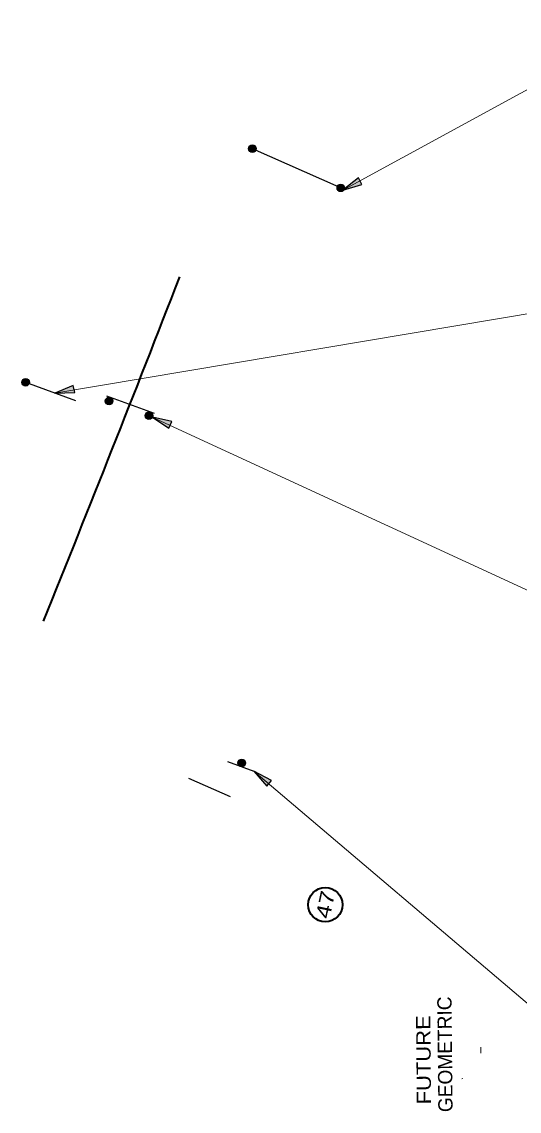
# Model space of a CAD drawing. Extents: x 2363411 to 2369702, y 6977197 to 6988655.
# Drawn here: x 2365294 to 2365781, y 6980619 to 6981687 of the extents above; entities that cross this region are included whole.
import ezdxf
from ezdxf.enums import TextEntityAlignment as Align

# ---------------------------------------------------------------- set-up
doc = ezdxf.new("R2010")
doc.units = 0
doc.header["$LTSCALE"] = 5.6
for name, color, linetype, lineweight in [('1', 7, 'Continuous', 25), ('15', 7, 'Continuous', 13), ('17', 7, 'Continuous', 35), ('23', 7, 'Continuous', 25), ('3', 7, 'Continuous', 13)]:
    doc.layers.add(name, color=color, linetype=linetype, lineweight=lineweight)

msp = doc.modelspace()

# ---------------------------------------------------------------- hatches: boundary and pattern name
at = {"layer": '1'}
for points in [[(2365516.54, 6981560.394, 1), (2365522.419, 6981564.992, 1)], [(2365607.98, 6981522.117), (2365626.692, 6981527.718), (2365623.395, 6981534.116)], [(2365603.151, 6981522.012, 1), (2365609.03, 6981526.609, 1)], [(2365300.1, 6981336.265, 1), (2365294.635, 6981331.182, 1)], [(2365325.995, 6981323.206), (2365345.523, 6981323.654), (2365344.049, 6981330.689)], [(2365381.831, 6981317.867, 1), (2365376.366, 6981312.784, 1)], [(2365420.93, 6981303.592, 1), (2365415.465, 6981298.509, 1)], [(2365421.538, 6981299.498), (2365437.793, 6981288.666), (2365440.62, 6981295.275)], [(2365511.779, 6980963.106, 1), (2365506.314, 6980958.023, 1)], [(2365520.975, 6980952.631), (2365533.575, 6980937.705), (2365538.129, 6980943.266)]]:
    msp.add_hatch(color=256, dxfattribs=at).paths.add_polyline_path(points)

# ---------------------------------------------------------------- linework, layer by layer
for p, q in [((2365604.484, 6981525.128), (2365519.48, 6981562.693)), ((2365297.357, 6981333.718), (2365346.184, 6981315.794)), ((2365376.543, 6981320.437), (2365423.194, 6981303.312)), ((2365495.118, 6980962.133), (2365520.812, 6980952.701))]:
    msp.add_line(p, q, dxfattribs=at)
at = {"layer": '1', "lineweight": 13}
for p, q in [((2365325.995, 6981323.206), (2365947.601, 6981427.566)), ((2365421.362, 6981299.52), (2365868.555, 6981093.178)), ((2365520.812, 6980952.701), (2365803.961, 6980712.038))]:
    msp.add_line(p, q, dxfattribs=at)
msp.add_lwpolyline([(2365607.98, 6981522.117), (2365840.659, 6981648.883), (2366127.574, 6981817.426)], dxfattribs=at)
at = {"layer": '1'}
for points in [[(2365607.98, 6981522.117), (2365626.692, 6981527.718), (2365623.395, 6981534.116)], [(2365325.995, 6981323.206), (2365345.523, 6981323.654), (2365344.049, 6981330.689)], [(2365421.538, 6981299.498), (2365437.793, 6981288.666), (2365440.62, 6981295.275)], [(2365520.975, 6980952.631), (2365533.575, 6980937.705), (2365538.129, 6980943.266)]]:
    msp.add_lwpolyline(points, close=True, dxfattribs=at)
for centre in [(2365519.48, 6981562.693), (2365606.09, 6981524.31), (2365297.367, 6981333.723), (2365379.098, 6981315.325), (2365418.197, 6981301.051), (2365509.047, 6980960.565)]:
    msp.add_circle(centre, 3.732, dxfattribs=at)
at = {"layer": '1', "lineweight": 35}
msp.add_arc((2344071.149, 6989699.388), 22918.312, 337.96111, 338.86822, dxfattribs=at)
at = {"layer": '15'}
msp.add_line((2365743.26, 6980676.066), (2365743.24, 6980682.065), dxfattribs=at)
at = {"layer": '17'}
msp.add_circle((2365590.886, 6980821.605), 16.828, dxfattribs=at)
at = {"layer": '23'}
msp.add_line((2365456.809, 6980945.679), (2365497.564, 6980927.573), dxfattribs=at)
at = {"layer": '3'}
msp.add_line((2365725.674, 6980651.142), (2365724.713, 6980651.113), dxfattribs=at)

# ---------------------------------------------------------------- texts
at = {"layer": '1'}
msp.add_text('GEOMETRIC', height=14, rotation=90.554, dxfattribs=at).set_placement((2365715.09, 6980675.071), align=Align.CENTER)
at = {"layer": '1', "width": 1.15}
msp.add_text('FUTURE ', height=14, rotation=90.554, dxfattribs=at).set_placement((2365694.114, 6980672.645), align=Align.CENTER)
at = {"layer": '17', "width": 1.3}
msp.add_text('47', height=14, rotation=77.939, dxfattribs=at).set_placement((2365597.757, 6980820.261), align=Align.CENTER)

doc.saveas('drawing.dxf')
